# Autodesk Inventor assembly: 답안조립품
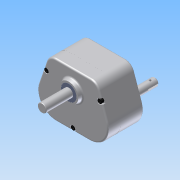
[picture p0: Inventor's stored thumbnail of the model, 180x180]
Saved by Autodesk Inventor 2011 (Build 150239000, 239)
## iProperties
Created: 2014-12
Part Number: 답안조립품
Document SubType Name: Assembly
Designer: SDA24
Author: SDA24
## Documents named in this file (14)
- C:\441208V1038\답안조립품.iam
- C:\441208V1038\M 5 x 35.ipt
- C:\441208V1038\멈춤링.ipt
- C:\441208V1038\메인기어.ipt
- C:\441208V1038\메인축.ipt
- C:\441208V1038\베어링- 6202.ipt
- C:\441208V1038\베어링- 6203.ipt
- C:\441208V1038\서브기어.ipt
- C:\441208V1038\서브축.ipt
- C:\441208V1038\오일시일-D-15.ipt
- C:\441208V1038\오일시일-D-17.ipt
- C:\441208V1038\커버.ipt
- C:\441208V1038\키5x5.ipt
- C:\441208V1038\부품1.ipt
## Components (15 placed, 6 different names)
1. KS B 1003 - 미터 M 5 x 35:1
2. KS B 1336 17 x 1:1 — 각도:5
3. KS B 2023 6202 - 15 x 35 x 11:1
4. KS B 2023 6203 - 17 x 40 x 12:1
5. KS B 2804 D D - 15 30 7:1
6. KS B 2804 D D - 17 30 8:1
7. KS B 2023 6203 - 17 x 40 x 12:2
8. KS B 2023 6202 - 15 x 35 x 11:2
9. KS B 2023 6203 - 17 x 40 x 12:3
10. KS B 2023 6203 - 17 x 40 x 12:4
11. KS B 1336 17 x 1:2 — 각도:4
12. KS B 1336 17 x 1:3
13. KS B 2804 D D - 15 30 7:2
14. KS B 1003 - 미터 M 5 x 35:2
15. KS B 1003 - 미터 M 5 x 35:3
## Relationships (2: Angle 2)
- 각도:4 [Angle]: KS B 1336 17 x 1:2
- 각도:5 [Angle]: KS B 1336 17 x 1:1
